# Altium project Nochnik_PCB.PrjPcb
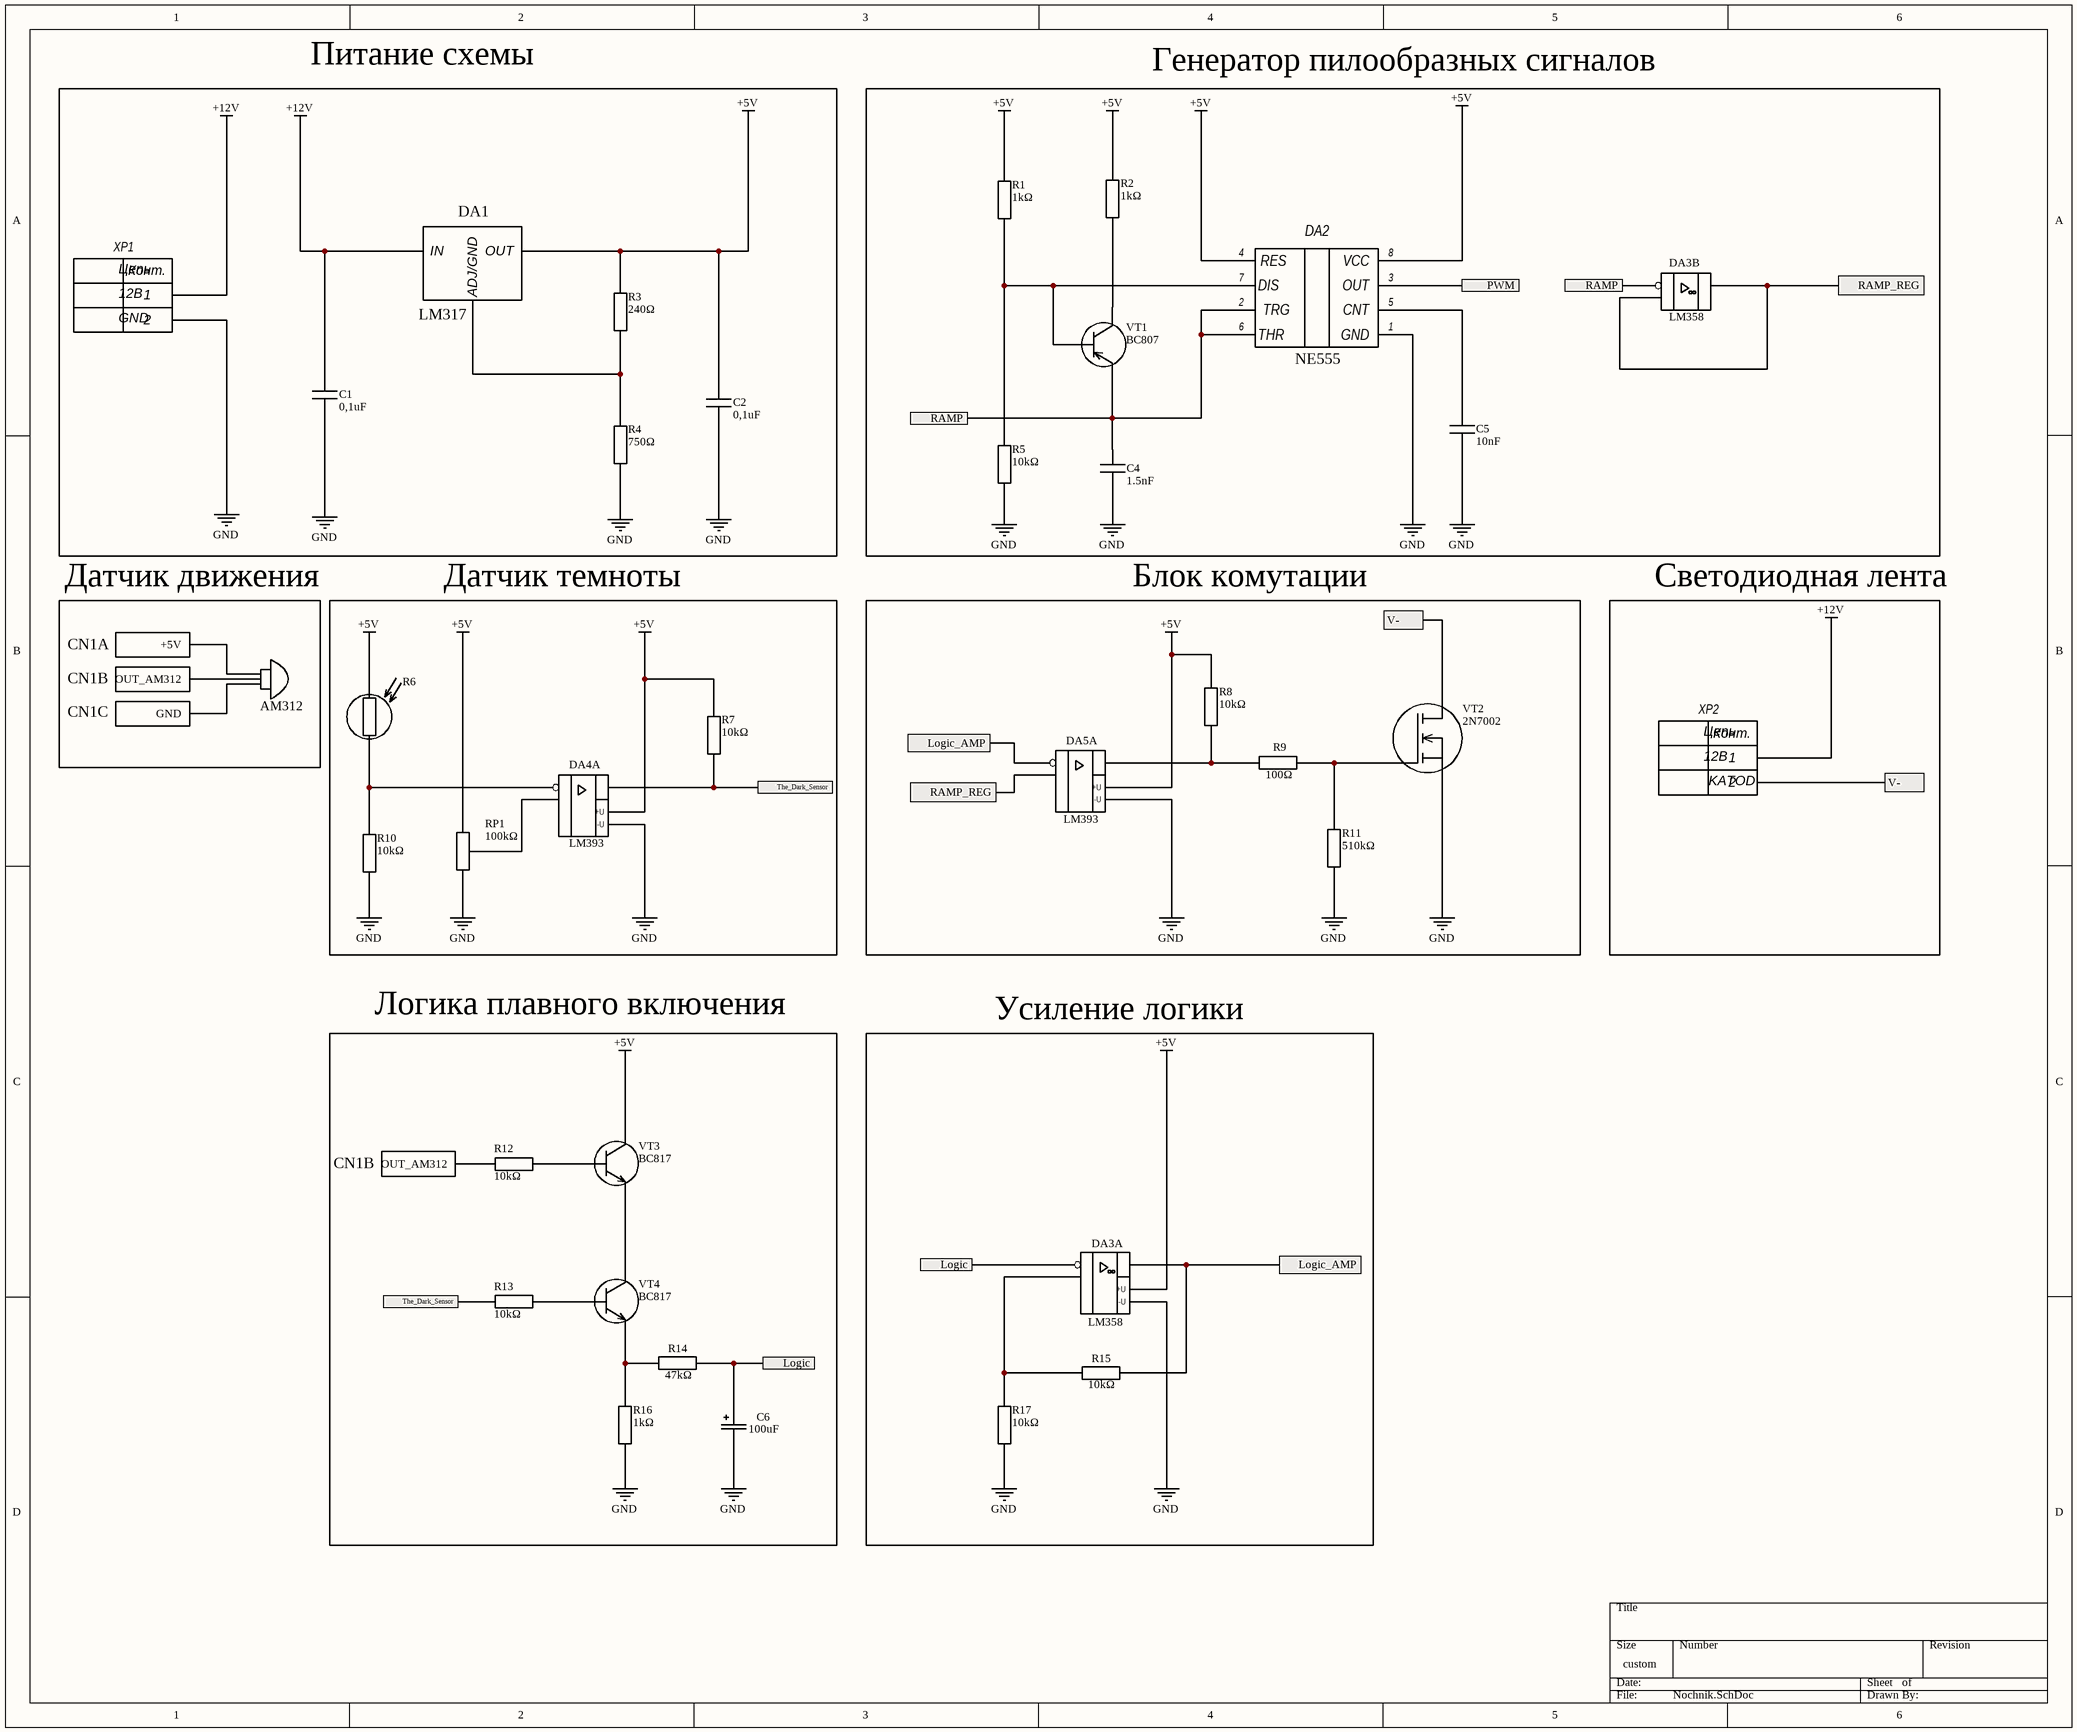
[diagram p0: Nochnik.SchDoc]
1 sheet, 37 parts. Net scope: flat (ports and power ports of the same name join across sheets).
Board file: Nochnik.PcbDoc

## Sheet Nochnik.SchDoc
size 420 x 350 mm; SheetNumber: 1; SheetTotal: 1

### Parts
(Parts that share a designator on the sheet are numbered #1, #2 ... from top to bottom, then left to right.)
*  AM312
C1  0,1uF  [CAP0805]
C2  0,1uF  [CAP0805]
C4  1.5nF  [CAP0805]
C5  10nF  [CAP0805]
C6  (no value)  [CAP_ELECTROLIT]
CN1#1  DS1023  [PLS-3]  (value not drawn)  (parts A,B,C of 3)
CN1#2  DS1023  [PLS-3]  (value not drawn)  (part B of 3)
DA1  LM317  [SOT-223]
DA2  NE555  [NE555]
DA3  LM358  [SOIC-8]  (parts A,B of 2)
DA4  LM393  [LM393]  (part A of 2)
DA5  LM393  [LM393]  (part A of 2)
R1  1kΩ  [Res]
R2  1kΩ  [Res]
R3  240Ω  [Res]
R4  750Ω  [Res]
R5  10kΩ  [Res]
R6  10K  [Photo_Res]  (value not drawn)
R7  10kΩ  [Res]
R8  10kΩ  [Res]
R9  100Ω  [Res]
R10  10kΩ  [Res]
R11  510kΩ  [Res]
R12  10kΩ  [Res]
R13  10kΩ  [Res]
R14  47kΩ  [Res]
R15  10kΩ  [Res]
R16  1kΩ  [Res]
R17  10kΩ  [Res]
RP1  100kΩ  [PR]
VT1  BC807  [BC807]
VT2  2N7002  [2N7002]
VT3  BC817  [BC817]
VT4  BC817  [BC817]
XP1  TB-11A  [TB-11A]  (value not drawn)
XP2  TB-11A  [TB-11A]  (value not drawn)

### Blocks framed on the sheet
Питание схемы: C1 C2 DA1 R3 R4 XP1
Датчик движения: * CN1#1
Датчик темноты: DA4 R6 R7 R10 RP1
Блок комутации: DA5 R8 R9 R11 VT2
Светодиодная лента: XP2

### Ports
Logic (see Nochnik[3C]), Logic (see Nochnik[3D]), Logic_AMP (see Nochnik[3B]), Logic_AMP (see Nochnik[4C]), PWM, RAMP (see Nochnik[3A]), RAMP (see Nochnik[5A]), RAMP_REG (see Nochnik[3B]), RAMP_REG (see Nochnik[6A]), The_Dark_Sensor (see Nochnik[2D]), The_Dark_Sensor (see Nochnik[3B]), V- (see Nochnik[5B]), V- (see Nochnik[6B])

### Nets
+5V: C2.2 DA1.2(OUT) DA2.4(RES) DA2.8(VCC) DA3.8(+U) DA4.8(+U) DA5.8(+U) R1.2 R2.2 R3.2 R6.1 R7.2 R8.2 RP1.1 VT3.3
+12V: C1.2 DA1.1(IN) XP1.1 XP2.1
GND: C1.1 C2.1 C4.1 C5.1 C6.1 DA2.1(GND) DA3.4(-U) DA4.4(-U) DA5.4(-U) R4.1 R5.1 R10.1 R11.1 R16.2 R17.2 RP1.2 VT2.2(S) XP1.2
Net*_+5V: *.+5V CN1#1.+5V
Net*_GND: *.GND CN1#1.GND
Net*_OUT: *.OUT CN1#1.2(OUT_AM312)
NetC4_2: C4.2 DA2.2(TRG) DA2.6(THR) DA3.5 VT1.2 ; port RAMP
NetC5_2: C5.2 DA2.5(CNT)
NetC6_2: C6.2 DA3.3 R14.2 ; port Logic
NetCN1#2_2: CN1#2.2(OUT_AM312) R12.2
NetDA1_3: DA1.3(ADJ/GND) R3.1 R4.2
NetDA2_3: DA2.3(OUT) ; port PWM
NetDA2_7: DA2.7(DIS) R1.1 R5.2 VT1.1
NetDA3_1: DA3.1 DA5.3 R15.2 ; port Logic_AMP
NetDA3_2: DA3.2 R15.1 R17.1
NetDA3_6: DA3.6 DA3.7 DA5.2 ; port RAMP_REG
NetDA4_1: DA4.1 R7.1 R13.2 ; port The_Dark_Sensor
NetDA4_2: DA4.2 RP1.3
NetDA4_3: DA4.3 R6.2 R10.2
NetDA5_1: DA5.1 R8.1 R9.2
NetR2_1: R2.1 VT1.3
NetR9_1: R9.1 R11.2 VT2.1(G)
NetR12_1: R12.1 VT3.1
NetR13_1: R13.1 VT4.1
NetR14_1: R14.1 R16.1 VT4.2
NetVT2_3: VT2.3(D) XP2.2 ; port V-
NetVT3_2: VT3.2 VT4.3

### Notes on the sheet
- Генератор пилообразных сигналов
- Логика плавного включения
- Усиление логики
- (near C6) 100uF

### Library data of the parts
C1 C2 C4 C5 = Cap: Value: 100nF
C6 = CAP_ELEC
CN1#1 CN1#2 = TERMINAL_03P: DS1023-1x4
DA1 = LM317: SOT-223
DA2 = NE555: NE555, SOIC8; Model: Таймер NE555DR TEXAS INSTRUMENTS
DA3 = LM358: LM358, SO8; Model: ОУ LM358A TEXAS INSTRUMENTS
DA4 DA5 = LM393: LM358, SO8; Model: ОУ LM358A TEXAS INSTRUMENTS
R1-R5 R7-R17 = Res: Value: 10K
R6 = Photo_Res
RP1 = CA6V: Trimmer potentiometer CA6V; Value: 10k
VT1 = BC807: Name: 2SC2712
VT3 VT4 = BC817: Name: 2SC2712
XP1 = TB-11A: Клеммник 2-контактный, 5мм, прямой; Sig1: Signal1; Sig2: Signal2; InMOP: 0; Current: 10 А; Voltage: 250 В
XP2 = TB-11A_1: Клеммник 2-контактный, 5мм, прямой; Sig1: Signal1; Sig2: Signal2; InMOP: 0; Current: 10 А; Voltage: 250 В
